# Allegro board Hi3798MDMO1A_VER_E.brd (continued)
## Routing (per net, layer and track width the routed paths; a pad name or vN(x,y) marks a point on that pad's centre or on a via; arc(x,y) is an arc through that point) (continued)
DDR_DQ9: length 9.5
  TOP w0.127: U3.C3 42.75,43.45 43.15,43.05 45.28,43.05 48.54,39.8 49.61,39.8 50.01,39.4 U1.K2
DDR_DQ10: length 12.4
  TOP w0.127: U1.M5 52.72,37.8 v2(52.32,37.4) ; v2(42.92,39.85) U3.C8
  BOTTOM w0.127: v2(52.32,37.4) 51.92,37.8 48.4,37.8 45.31,40.89 43.96,40.89 v2(42.92,39.85)
DDR_DQ11: length 14.7
  TOP w0.127: U1.J3 50.72,39.8 50.12,39.8 49.51,40.41 48.49,40.41 44.93,43.97 44.93,45.72 44.54,46.1 42.39,46.1 42.12,45.84 42.12,44.65 U3.C2
DDR_DQ12: length 9.6
  TOP w0.127: v2(44.67,40.41) 44.51,40.25 U3.A7 ; U1.N4 v2(51.52,36.6)
  BOTTOM w0.127: v2(51.52,36.6) 50.99,37.13 48.44,37.13 45.15,40.41 v2(44.67,40.41)
DDR_DQ13: length 9.8
  TOP w0.127: U3.A2 v2(44.52,44.65) ; U1.J4 v2(51.52,40.6)
  BOTTOM w0.127: v2(44.52,44.65) 45.99,44.65 49.65,40.99 50.88,40.99 51.13,40.99 v2(51.52,40.6)
DDR_DQ14: length 10.6
  TOP w0.127: U1.P4 v2(51.52,35.8) ; v2(43.72,39.85) U3.B8
  BOTTOM w0.127: v2(51.52,35.8) 51.35,35.8 50.53,36.62 48.31,36.62 45.08,39.85 v2(43.72,39.85)
DDR_DQ15: length 10.6
  TOP w0.127: U1.J5 v2(52.32,40.6) ; U3.A3 v2(44.52,43.85)
  BOTTOM w0.127: v2(52.32,40.6) 51.93,40.2 49.68,40.2 46.03,43.85 v2(44.52,43.85)
DDR_DQ16: length 17.1
  TOP w0.127: U1.T5 v2(52.32,35) ; U6.E3 v2(40.52,27.44)
  BOTTOM w0.127: v2(40.52,27.44) 40.52,28.1 41.24,28.83 41.24,29.34 46.93,35.02 50.26,35.02 50.68,34.6 51.93,34.6 v2(52.32,35)
DDR_DQ17: length 20.1
  TOP w0.127: U6.F7 40.51,23.45 40.51,22.83 40.68,22.66 41.16,22.66 41.31,22.52 41.31,21.27 41.75,20.83 44.92,20.83 52.03,27.93 52.03,29.26 52.28,29.51 52.28,29.89 52.72,30.33 U1.AA5
DDR_DQ18: length 13.7
  TOP w0.127: U6.F2 40.52,28.25 40.52,28.87 46.32,34.67 48.47,34.67 48.8,35 49.67,35 50.06,34.6 U1.T2
DDR_DQ19: length 19.4
  TOP w0.127: U1.AB5 52.72,29.52 52.31,29.1 52.31,27.67 45.08,20.45 41.35,20.45 40.51,21.28 40.51,22.4 40.12,22.79 U6.F8
DDR_DQ20: length 18.8
  TOP w0.127: U1.R5 v2(52.32,35.8) ; U6.H3 v2(38.92,27.44)
  BOTTOM w0.127: v2(52.32,35.8) 51.93,35.4 50.86,35.4 50.58,35.68 46.95,35.68 40.86,29.59 40.86,28.96 40.1,28.19 40.1,27.81 39.73,27.44 v2(38.92,27.44)
DDR_DQ21: length 21.7
  TOP w0.127: U1.AC6 53.52,27.67 45.54,19.68 40.71,19.68 38.89,21.51 38.89,22.4 38.52,22.77 U6.H8
DDR_DQ22: length 15.9
  TOP w0.127: U1.T3 50.83,34.6 50.46,34.97 50.2,34.97 49.92,35.25 48.6,35.25 48.4,35.05 46.06,35.05 40.86,29.84 40.1,29.84 39.72,29.46 39.72,28.24 U6.G2
DDR_DQ23: length 23.3
  TOP w0.127: U6.H7 38.92,23.44 38.92,22.85 39.11,22.66 39.51,22.66 39.69,22.49 39.69,21.34 40.97,20.07 45.34,20.07 53.15,27.88 53.15,30.22 U1.AA6
DDR_DQ24: length 17.6
  TOP w0.127: U6.D7 42.12,23.44 42.12,22.8 42.28,22.64 42.79,22.64 42.94,22.49 42.94,21.6 43.33,21.21 44.75,21.21 51.72,28.18 51.72,29.36 51.49,29.59 51.49,30.17 U1.AA4
DDR_DQ25: length 11.3
  TOP w0.127: U6.C3 42.92,27.45 42.92,30 46.72,33.8 U1.U1
DDR_DQ26: length 13
  TOP w0.127: U6.C8 42.83,23.04 43.23,22.65 45.63,22.65 51.47,28.49 51.47,29.18 51.12,29.53 U1.AB3
DDR_DQ27: length 13.2
  TOP w0.127: U6.C2 42.11,28.25 42.11,29.82 46.5,34.21 48.58,34.21 48.68,34.11 49.17,34.11 49.26,34.21 50.71,34.21 U1.U3
DDR_DQ28: length 8.3
  TOP w0.127: U1.AC2 45.32,23.99 44.27,23.99 U6.A7
DDR_DQ29: length 11.4
  TOP w0.127: U1.T4 v2(51.52,34.2) ; U6.A2 44.63,27.84 v2(45.03,28.24)
  BOTTOM w0.127: v2(45.03,28.24) 45.03,29.69 49.53,34.2 v2(51.52,34.2)
DDR_DQ30: length 10.9
  TOP w0.127: U1.AB2 50.73,29.39 50.73,28.88 45.31,23.45 43.72,23.45 U6.B8
DDR_DQ31: length 12.6
  TOP w0.127: U1.U4 v2(52.32,34.2) ; U6.A3 v2(44.52,27.44)
  BOTTOM w0.127: v2(44.52,27.44) 45.06,27.44 45.69,28.07 45.69,29.46 50.03,33.8 51.93,33.8 v2(52.32,34.2)
DDR_DQS0N: length 13
  TOP w0.114: U1.L1 49.43,38.69 49.27,38.69 49.16,38.58 49.16,38.47 49.05,38.35 48.82,38.35 48.7,38.47 48.7,38.58 48.59,38.69 48.4,38.69 45.05,42.04 40.1,42.04 39.58,42.55 39.58,43.19 U3.G3
DDR_DQS0P: length 13.1
  TOP w0.114: U1.L2 49.96,38.96 48.51,38.96 45.16,42.3 40.21,42.3 39.85,42.66 39.85,43.19 U3.F3
DDR_DQS1N: length 10.3
  TOP w0.114: U3.B7 43.05,40.52 43.05,40.71 43.24,40.89 44.93,40.89 48.37,37.45 50.77,37.45 U1.M3
DDR_DQS1P: length 10.3
  TOP w0.114: U1.M2 50.24,37.71 49.93,37.71 49.81,37.83 49.81,37.99 49.7,38.1 49.47,38.1 49.35,37.99 49.35,37.83 49.24,37.71 48.48,37.71 45.04,41.16 43.13,41.16 42.78,40.82 42.78,40.52 U3.C7
DDR_DQS2N: length 17.5
  TOP w0.114: U1.V2 50.24,33.08 50.08,33.08 49.94,32.94 49.7,32.94 49.57,33.08 49.32,33.08 49.19,32.94 48.95,32.94 48.81,33.08 48.57,33.08 48.44,32.94 48.2,32.94 48.06,33.08 47.86,33.08 45.69,30.91 45.69,27.14 44.29,25.74 40.02,25.74 39.71,26.05 39.71,26.65 U6.G3
DDR_DQS2P: length 17.5
  TOP w0.114: U1.V3 50.9,33 50.55,33.35 47.75,33.35 45.42,31.02 45.42,27.25 44.18,26 40.13,26 39.97,26.16 39.97,26.9 U6.F3
DDR_DQS3N: length 13
  TOP w0.114: U1.W2 50.02,32.2 49.61,31.8 48.78,31.8 48.61,31.62 48.61,28.45 44.8,24.64 43.28,24.64 43.05,24.41 43.05,24.11 U6.B7
DDR_DQS3P: length 12.9
  TOP w0.114: U1.W1 49.39,32.06 48.67,32.06 48.34,31.73 48.34,31.45 48.23,31.33 48.23,31.09 48.34,30.98 48.34,30.74 48.23,30.62 48.23,30.38 48.34,30.27 48.34,30.03 48.23,29.91 48.23,29.67 48.34,29.56 48.34,29.31 48.23,29.2 48.23,28.96 48.34,28.84 48.34,28.56 44.68,24.9 43.17,24.9 42.78,24.52 42.78,24.11 U6.C7
DDR_ODT: length 85.5
  TOP w0.127: U3.K1 v2(37.32,44.65) ; U6.K1 37.23,28.95 37.23,29.8 v2(36.89,30.13) 36.61,30.41 36.61,30.41 33.08,33.94 v2(29.81,33.94) ; U1.AB15 v2(61.12,29.4)
  BOTTOM w0.127: v2(36.89,30.13) 36.61,30.41 36.61,37.71 36.97,38.07 36.97,40.85 36.57,41.26 36.57,43.9 v2(37.32,44.65) ; v2(29.81,33.94) 28.03,32.17 28.03,27.43 29.43,26.04 29.43,25.65 28.81,25.04 28.81,21.19 32.52,17.48 32.52,16.43 36,12.95 46.69,12.95 60.73,26.99 60.73,29 v2(61.12,29.4)
DDR_PLL: length 9.7
  TOP w0.254: v2(57.92,35) 57.91,35 56.59,35 55.55,35 55.01,35.55 v2(55.01,36.47)
  TOP w0.305: U1.N8 55.12,36.58 v2(55.01,36.47) ; U1.T12 v2(57.92,35)
  BOTTOM w0.381: v2(57.92,35) 57.92,35 C270.1 ; LB7.1 54.53,38.61 54.53,38.07 54.86,37.74 C11.1 54.86,36.62 v2(55.01,36.47) 55.01,36.15 C264.1
DDR_RASN: length 90
  TOP w0.127: U1.AB16 v2(61.12,30.2) ; U6.J3 38.06,27.39 38.06,28.96 37.81,29.21 37.81,30.1 v2(37.05,30.86) 33.31,34.6 v2(29.81,34.6) ; U3.J3 v2(37.32,43.85)
  BOTTOM w0.127: v2(61.12,30.2) 61.55,29.77 61.55,26.74 47,12.19 35.68,12.19 31.46,16.41 31.46,17.91 27.65,21.72 27.65,32.45 v2(29.81,34.6) ; v2(37.32,43.85) 36.79,43.33 36.79,41.41 37.28,40.93 37.28,37.9 37,37.62 37,30.92 v2(37.05,30.86)
DDR_RESETN: length 76.5
  TOP w0.127: v1(36.92,14.22) 32.46,14.22 28.49,18.19 28.49,25.35 29.91,26.76 C314.1 30.34,26.78 30.45,26.67 32.23,26.67 32.46,26.9 32.46,27.33 32.12,27.67 U6.T2 31.56,27.84 27.48,31.93 27.48,36.27 28.42,37.21 28.42,41.8 29.71,43.09 32.32,43.09 32.52,43.29 v2(32.52,43.85) U3.T2 ; U1.AB13 v2(59.52,29.4)
  BOTTOM w0.127: v2(32.52,43.85) 32.51,43.85 C313.1 ; v2(59.52,29.4) 59.4,29.28 R24.1 58.92,28.6 58.26,27.94 58.26,27.05 45.43,14.22 v1(36.92,14.22)
DDR_VREF_A_CA: length 6.8
  TOP w0.203: 35.93,38.19 35.72,38.39 35.72,39.05 U3.M8
  TOP w0.381: R55.1 C86.1 R33.2 C49.2 35.75,36.44 35.93,36.61 35.93,38.19
DDR_VREF_A_DQ: length 3.9
  TOP w0.254: U3.H1 v2(38.12,45.45)
  BOTTOM w0.381: v2(38.12,45.45) 37.91,45.66 C208.2 R54.2 C271.1 R75.1
DDR_VREF_B_CA: length 6.6
  TOP w0.203: 35.97,21.65 35.7,21.92 35.7,22.66 U6.M8
  TOP w0.381: R93.1 C87.1 R92.2 C66.2 36.08,21.54 35.97,21.65
DDR_VREF_B_DQ: length 4.5
  TOP w0.305: v2(38.59,29.7) 38.59,28.72 U6.H1
  BOTTOM w0.381: v2(38.59,29.7) 38.7,29.81 C308.1 R84.1 C223.2 R78.2
DDR_WEN: length 75.3
  TOP w0.127: U1.Y13 59.12,31.4 v2(58.72,31) ; v1(33.9,16.76) 33.58,17.08 30.83,19.83 30.83,23.71 31.76,24.64 34.52,24.64 36.12,26.24 U6.L3 36.12,27.28 35.66,27.73 35.66,27.99 35.37,28.28 35.12,28.28 34.91,28.48 34.91,29.45 34.26,30.1 32.61,30.1 31.97,30.73 31.34,30.73 29,33.07 29,35.26 29.94,36.2 29.94,39.24 31.63,40.93 34.18,40.93 36.12,42.87 U3.L3
  BOTTOM w0.127: v2(58.72,31) 58.72,28.91 57.88,28.07 57.88,27.3 45.31,14.73 35.93,14.73 v1(33.9,16.76)
FE_1V1: length 1.3
  TOP w0.305: U1.G10 v2(56.32,41.4)
  BOTTOM w0.381: C248.1 56.17,41.25 v2(56.32,41.4)
FE_3V3: length 0.6
  TOP w0.305: U1.E5 52.72,43.4 v2(52.32,43.8)
HDMI_TX0N: length 42.9
  TOP w0.114: J26.9 47.72,78.17 47.29,77.74 47.29,76.95 46.54,76.2 46.54,75.76 46.65,75.64 U24.9 U24.2 46.65,73.64 46.54,73.52 46.54,67.6 50.4,63.74 50.4,59.96 59.36,51 59.36,50.19 61.86,47.69 61.86,44.54 U1.D16
HDMI_TX0P: length 42.9
  TOP w0.114: U1.C16 61.6,45.07 61.6,46.4 61.44,46.56 61.44,46.86 61.6,47.02 61.6,47.58 61.49,47.69 61.33,47.69 61.25,47.61 61.09,47.61 60.93,47.78 60.93,47.94 61,48.01 61,48.17 60.84,48.33 60.68,48.33 60.61,48.26 60.44,48.26 60.28,48.42 60.28,48.58 60.36,48.66 60.36,48.82 59.09,50.08 59.09,50.89 50.13,59.85 50.13,63.63 46.27,67.49 46.27,73.51 46.15,73.63 U24.1 U24.10 46.15,75.62 46.27,75.74 46.27,76.31 47.02,77.06 47.02,77.8 46.72,78.11 J26.7
HDMI_TX1N: length 42
  TOP w0.114: J26.6 46.22,78.23 45.75,77.76 45.75,76.98 44.86,76.09 44.86,75.81 44.98,75.69 U23.6 U23.5 44.98,73.7 44.87,73.58 44.87,67.85 49.38,63.33 49.38,58.77 57.41,50.75 57.75,50.75 58.35,50.15 58.35,49.97 58.35,49.8 61.07,47.08 61.07,46.57 61.07,46.15 U1.B15
HDMI_TX1P: length 42
  TOP w0.114: J26.4 45.22,78.08 45.49,77.82 45.49,77.09 44.6,76.2 44.6,75.81 44.48,75.7 U23.7 U23.4 44.48,73.69 44.6,73.57 44.6,67.74 49.12,63.22 49.12,58.66 57.3,50.48 57.64,50.48 58.08,50.04 58.08,49.69 58.79,48.99 58.79,48.83 58.71,48.76 58.71,48.6 58.87,48.43 59.04,48.43 59.11,48.51 59.27,48.51 59.43,48.34 59.43,48.18 59.36,48.11 59.36,47.95 59.52,47.79 59.68,47.79 59.76,47.86 59.92,47.86 60.08,47.7 60.08,47.54 60.08,47.36 60.22,47.21 60.4,47.21 60.56,47.21 60.8,46.97 60.8,46.68 U1.A15
HDMI_TX2N: length 42.9
  TOP w0.114: J26.3 44.72,78.12 44.38,77.79 44.38,77.3 43.36,76.28 43.36,75.73 43.48,75.61 U23.9 U23.2 43.48,73.57 43.35,73.44 43.35,67.76 48.37,62.75 48.37,58.39 60.28,46.47 60.28,45.36 U1.C14
HDMI_TX2P: length 42.8
  TOP w0.114: U1.B14 60.02,45.89 60.02,46.36 59.8,46.58 59.64,46.58 59.56,46.5 59.4,46.5 59.24,46.66 59.24,46.82 59.32,46.9 59.32,47.06 59.16,47.22 59,47.22 58.92,47.14 58.75,47.14 58.59,47.3 58.59,47.47 58.67,47.55 58.67,47.71 48.1,58.28 48.1,62.64 43.08,67.65 43.08,73.53 42.98,73.64 U23.1 U23.10 42.98,75.62 43.1,75.74 43.1,76.39 44.12,77.41 44.12,77.75 43.72,78.14 J26.1
HDMI_TX_1V1: length 1.1
  TOP w0.305: U1.G14 59.92,41.8 v2(60.32,41.4) U1.G15
HDMI_TX_3V3: length 0.6
  TOP w0.381: U1.E15 v2(60.32,43.8)
HDMI_TX_CEC: length 42.3
  TOP w0.127: J26.13 49.72,75.89 48.8,74.98 48.8,72.94 49.28,72.47 50.31,72.47 U4.3 50.31,71.89 49.92,71.5 R268.2 49.92,66.63 52.36,64.2 52.36,61.43 61.18,52.6 61.18,51.69 61.59,51.28 61.59,50.2 63.03,48.76 63.03,45.64 63.12,45.54 U1.C18
HDMI_TX_HOTPLUG: length 42.5
  TOP w0.127: U1.B19 63.92,45.8 63.92,46.08 64.32,46.48 64.32,46.88 63.79,47.42 63.79,49.14 62.58,50.35 62.58,51.82 61.94,52.45 61.94,53.06 53.76,61.25 53.76,68.5 52.84,69.41 C149.1 R8.2 52.84,71.89 52.81,71.91 U4.4 54.43,72.47 55.66,73.71 55.66,75.22 54.42,76.46 54.42,76.77 52.72,78.47 J26.19
HDMI_TX_SCL: length 42.7
  TOP w0.127: U1.D18 63.51,44.59 63.51,45.69 63.28,45.92 63.28,48.89 61.92,50.25 61.92,51.46 61.44,51.94 61.44,52.76 52.74,61.45 52.74,67.12 51.39,68.46 51.39,74.03 51.05,74.37 U4.1 50.31,75.35 50.69,75.73 R186.1 51.19,76.4 50.72,76.87 J26.15
HDMI_TX_SDA: length 40.1
  TOP w0.127: J26.16 51.22,78.09 52.97,76.34 R187.1 52.97,75.23 52.81,75.08 U4.6 52.07,74.37 51.75,74.05 51.75,68.62 53.12,67.25 53.12,61.48 61.69,52.91 61.69,52.2 62.25,51.64 62.25,50.3 63.53,49.02 63.53,46.98 U1.A19
HDMI_TXCN: length 42.4
  TOP w0.114: J26.12 49.22,78.23 48.84,77.85 48.84,77.04 48.04,76.23 48.04,75.75 48.15,75.64 U24.6 U24.5 48.15,73.62 48.05,73.52 48.05,67.61 51.42,64.25 51.42,60.46 55.86,56.02 57.73,54.15 57.9,54.15 58.03,54.28 58.41,54.28 58.89,53.8 58.89,53.42 58.76,53.28 58.76,53.12 59.08,52.8 59.24,52.8 59.38,52.93 59.76,52.93 60.24,52.45 60.24,52.07 60.11,51.94 60.11,51.77 60.47,51.41 60.47,50.48 62.67,48.28 62.67,46.15 U1.B17
HDMI_TXCP: length 42.4
  TOP w0.114: J26.10 48.22,78.21 48.58,77.85 48.58,77.15 47.77,76.34 47.77,75.79 47.65,75.67 U24.7 U24.4 47.65,73.65 47.79,73.52 47.79,67.5 51.15,64.14 51.15,60.35 57.62,53.88 58.01,53.88 58.14,54.01 58.3,54.01 58.63,53.69 58.63,53.53 58.49,53.39 58.49,53.01 58.97,52.53 59.35,52.53 59.49,52.67 59.65,52.67 59.97,52.34 59.97,52.18 59.84,52.05 59.84,51.66 60.2,51.3 60.2,50.37 60.4,50.17 60.4,50.01 60.36,49.97 60.36,49.81 60.52,49.65 60.68,49.65 60.72,49.69 60.88,49.69 61.04,49.53 61.04,49.36 61,49.32 61,49.16 61.16,49 61.33,49 61.37,49.04 61.53,49.04 61.69,48.88 61.69,48.72 61.65,48.68 61.65,48.51 61.81,48.35 61.97,48.35 62.01,48.39 62.18,48.39 62.4,48.17 62.4,46.68 U1.A17
IR_IN: length 33.6
  TOP w0.127: v1(70.4,11.05) 70.07,11.05 69.74,10.72 69.74,9.45 69.35,9.06 69.35,6.29 69.66,5.99 R140.1 70.14,4.87 70.09,4.82 D3.1 ; v1(65.87,25.62) 65.69,25.8 65.69,29.84 65.18,30.36 65.18,31.05 U1.Y21
  BOTTOM w0.127: v1(65.87,25.62) 65.87,25.03 69.06,21.84 69.06,15.88 71.34,13.59 71.34,12.95 70.4,12.01 v1(70.4,11.05)
LED0_BASE: length 44.8
  TOP w0.127: U1.B2 49.93,45.41 49.3,45.41 48.86,45.85 48.86,47.35 49.24,47.73 49.24,49.66 41.32,57.58 28.24,57.58 26,59.82 26,61.2 24.21,62.99 20.8,62.99 20.1,63.69 20.1,64.76 R26.2 R67.2
LED0_LINK_ACT: length 30.4
  TOP w0.127: v1(37.75,58.09) 41.45,58.09 49.62,49.91 49.62,47.66 49.12,47.15 49.12,46.2 U1.B1 ; R30.2 R79.2 v2(37.75,66.18)
  BOTTOM w0.127: v1(37.75,58.09) 38.7,59.04 38.7,65.23 v2(37.75,66.18)
LED_GREEN: length 29.3
  TOP w0.127: U1.AB22 65.95,29.42 65.95,26.31 v1(66.73,25.52)
  BOTTOM w0.127: R48.1 67.28,9.72 66.95,9.4 66.58,9.4 R3.2 ; R48.1 67.65,9.27 67.78,9.14 69.69,9.14 70.87,10.33 70.87,11.98 71.72,12.83 71.72,13.72 69.44,16 69.44,22.23 66.73,24.93 v1(66.73,25.52) ; R48.1 R22.1
LED_RED: length 27.3
  TOP w0.127: v1(67.47,25.07) 67.47,25.51 66.28,26.7 66.28,28.59 66.32,28.63 U1.AC22
  BOTTOM w0.127: v1(67.47,25.07) 69.82,22.72 69.82,16.13 72.1,13.84 72.1,12.7 71.18,11.78 71.18,10.12 69.51,8.45 R60.2 R39.1 R31.1
MUTE_CTRL: length 31.6
  TOP w0.127: R90.1 55.66,70.17 54.14,68.65 54.14,61.27 62.2,53.21 62.2,52.67 64.8,50.06 64.8,47.42 65.08,47.14 65.08,46.43 64.86,46.2 64.59,46.2 64.31,45.93 64.31,45.39 U1.C19
NF_ALE_EMMC_PWREN: length 33.3
  TOP w0.127: U19.17 84.01,47.27 83.25,48.03 80.26,48.03 79.98,47.75 79.98,45.59 81.25,44.32 81.25,37.97 79.48,36.2 68.25,36.2 68.13,36.09 66.23,36.09 65.72,36.6 65.12,36.6 U1.N20
NF_CLE: length 33
  TOP w0.127: U1.N21 65.75,37 66.4,36.34 67.98,36.34 68.09,36.46 79.22,36.46 80.87,38.1 80.87,44.2 79.65,45.42 79.65,47.83 80.13,48.31 83.61,48.31 84.51,47.41 U19.16
NF_CSN0_EMMC_CMD: length 47.7
  TOP w0.127: v2(85.35,40.89) 85.35,41.06 87.54,43.25 87.54,44.32 88.01,44.8 U19.9 88.01,47.34 86.76,48.59 80,48.59 79.32,47.9 79.32,45.24 80.49,44.07 80.49,38.23 78.97,36.71 67.89,36.71 67.78,36.6 66.72,36.6 U1.N22
  TOP w0.254: v2(87.22,38.36) 87.51,38.66 U22.W5
  BOTTOM w0.127: v2(87.22,38.36) 86.7,37.85 86.33,37.85 85.86,38.32 85.86,39.84 85.57,40.12 R212.2 85.22,40.76 85.35,40.89 v2(85.35,40.89)
NF_DQ0_EMMC_D0: length 36.4
  TOP w0.127: v2(88.74,32.26) 88.51,32.48 U22.H3 ; v2(84.93,30.61) 84.55,30.61 82.51,28.57 U19.29 82.51,26.04 82.31,25.83 80.29,25.83 79.62,26.49 79.62,33.21 77.81,35.02 68.28,35.02 67.91,35.4 U1.R23
  BOTTOM w0.127: v2(88.74,32.26) 88.61,32.38 86.2,32.38 84.97,31.15 84.97,30.64 v2(84.93,30.61) 84.57,30.25 R189.2
NF_DQ1_EMMC_D1: length 36.3
  TOP w0.102: U1.R22 66.66,35.06 67.87,35.06 68.16,34.77
  TOP w0.127: 68.16,34.77 77.63,34.77 79.29,33.11 79.29,26.44 80.16,25.57 82.58,25.57 83.01,26 U19.30 v1(83.01,28.07) ; v2(87.6,31.5) 88.01,31.91 U22.H4
  BOTTOM w0.127: v2(87.6,31.5) 87.09,32 86.43,32 85.57,31.14 85.57,30.48 83.91,28.83 R12.2 82.92,28.16 v1(83.01,28.07)
NF_DQ2_EMMC_D2: length 37
  TOP w0.102: U1.R21 66.09,34.83 67.72,34.83 68.06,34.49
  TOP w0.127: v2(86.58,31.5) 86.58,31.75 87.51,32.68 U22.H5 ; 68.06,34.49 77.43,34.49 78.96,32.95 78.96,26.4 80.81,24.56 82.95,24.56 83.12,24.73 R29.2 83.51,25.46 U19.31 83.51,28.05 84.68,29.21 v2(85.57,29.21)
  BOTTOM w0.127: v2(86.58,31.5) 86.07,30.99 86.07,29.72 v2(85.57,29.21)
NF_DQ3_EMMC_D3: length 40.6
  TOP w0.089: U22.J2 88.76,33.62 88.76,33
  TOP w0.102: U1.T21 67.59,34.6 67.95,34.23
  TOP w0.127: 88.76,33 89.22,32.54 89.22,31.09 88.61,30.48 88.11,30.48 87.6,29.97 87.6,29.21 87.06,28.68 84.91,28.68 84.01,27.79 U19.32 84.01,24.95 R58.2 83.12,23.71 82.95,23.54 81.44,23.54 78.63,26.35 78.63,32.85 77.25,34.23 67.95,34.23
NF_DQ4_EMMC_D4: length 44.7
  TOP w0.089: U22.J3 88.26,33.62 88.26,33.01
  TOP w0.102: U1.T20 65.11,34.21 66.2,34.21 66.36,34.37 67.46,34.37 67.85,33.98
  TOP w0.127: v2(88.61,29.84) 88.11,29.34 88.11,28.6 88.51,28.19 U19.41 88.51,23.9 87.9,23.29 81.34,23.29 78.3,26.32 78.3,32.75 77.07,33.98 67.85,33.98 ; v2(88.74,31.24) 88.26,31.72 88.26,33.01
  BOTTOM w0.127: R176.2 89.84,31.24 v2(88.74,31.24) 88.61,31.11 v2(88.61,29.84)
NF_DQ5_EMMC_D5: length 45.8
  TOP w0.089: 87.76,33.06 87.76,33.62 U22.J4
  TOP w0.102: 67.75,33.73 67.34,34.14 66.66,34.14 U1.U22
  TOP w0.127: v2(87.6,30.61) 87.09,31.11 87.09,31.75 87.76,32.42 87.76,33.06 ; 67.75,33.73 76.84,33.73 77.97,32.6 77.97,26.29 81.23,23.03 88.15,23.03 89.01,23.9 U19.42 89.01,28.56 v2(88.61,28.96)
  BOTTOM w0.127: R177.2 89.75,31.75 88.61,31.75 87.6,30.73 v2(87.6,30.61) 87.6,29.97 v2(88.61,28.96)
NF_DQ6_EMMC_D6: length 46.6
  TOP w0.089: 87.26,33.22 87.26,33.52 87.51,33.77 U22.J5
  TOP w0.127: 87.26,33.22 87.26,32.94 86.07,31.75 86.07,31.11 v2(86.58,30.61) ; U1.U23 67.45,33.47 76.64,33.47 77.64,32.47 77.64,26.2 81.06,22.78 88.41,22.78 89.51,23.89 U19.43 89.51,29.33 v2(89.38,29.46)
  BOTTOM w0.127: v2(86.58,30.61) 86.58,30.23 88.36,28.45 89.12,28.45 89.38,28.7 v2(89.38,29.46) 89.38,29.72 89.67,30.02 90.05,30.02 R188.2
NF_DQ7_EMMC_D7_BOOT_SEL0: length 48.3
  TOP w0.089: U22.J6 86.76,33.62 86.76,32.99 86.52,32.74
  TOP w0.127: 86.52,32.74 85.69,31.92 85.69,30.48 86.58,29.59 v2(86.58,29.21) ; U1.U21 66.1,33.22 69.63,33.22 R82.1 70.39,33.22 76.46,33.22 77.31,32.37 77.31,26.15 80.93,22.53 88.66,22.53 90.01,23.88 U19.44 v1(90.01,28.07)
  BOTTOM w0.127: v2(86.58,29.21) 87.09,29.21 88.23,28.07 v1(90.01,28.07) 90.05,28.1 R202.2
NF_RDY0_EMMC_RST: length 53.5
  TOP w0.127: v2(90.62,37.33) 90.65,37.33 91.54,38.22 91.54,42.39 89.01,44.91 U19.7 89.01,47.35 87.22,49.15 79.75,49.15 78.66,48.06 78.66,44.88 79.72,43.81 79.72,38.48 79.09,37.85 68.8,37.85 68.23,37.27 67.65,37.27 67.53,37.38 65.93,37.38 U1.M21
  TOP w0.254: U22.U5 87.56,37.87 88,37.43 v2(88,35.99)
  BOTTOM w0.127: v2(88,35.99) 88,36.5 88.83,37.33 C115.1 R203.2 v2(90.62,37.33)
NF_REN_EMMC_CLK: length 42.3
  TOP w0.127: v2(86.16,40.89) 86.16,41.23 87.72,42.8 88.15,42.8 88.51,43.16 U19.8 88.51,47.34 86.99,48.87 79.88,48.87 78.99,47.98 78.99,45.06 80.1,43.94 80.1,38.35 79.09,37.34 R65.1
  TOP w0.254: U22.W6 87.01,38.84 86.54,38.37 v2(86.47,38.37)
  BOTTOM w0.127: v2(86.47,38.37) 86.16,38.68 v2(86.16,40.89)
NF_WEN_EMMC_DET: length 27.6
  TOP w0.127: U19.18 83.51,43.65 81.63,41.76 81.63,37.85 79.72,35.94 68.66,35.94 v2(68.33,35.61) 68.18,35.76 65.96,35.76 U1.P21
  BOTTOM w0.127: v2(68.33,35.61) 68.21,35.48 R56.2
NF_WP: length 5.2
  TOP w0.254: v2(82.66,43.58) 83.01,43.94 U19.19
  BOTTOM w0.381: v2(82.66,43.58) 82.08,43 R89.1 R215.2
PWR_OFF/ON: length 2.9
  TOP w0.127: R44.1 R51.1 68.32,40.67 67.85,40.2 U1.J23
RECOVERY: length 51.9
  TOP w0.127: U1.J22 66.32,40.41 65.95,40.79 65.95,41.55 67.62,43.23 67.62,45.03 67.9,45.31 67.9,47.47 66.25,49.12 66.25,50.95 63.98,53.22 63.98,61.19 66.54,63.75 69.18,63.75 71.28,65.85 71.28,75.14 R47.2 C42.2 70.61,83.85 S1.2
RF0: length 8.6
  TOP w0.127: L1.2 C64.1 17.48,11.83 arc(17.77,11.89) 18,12.05 20.17,14.22 arc(20.83,15.2) 21.07,16.37 U7.3
RF1: length 4
  TOP w0.127: L7.2 C50.1 17.64,15.13 arc(17.97,15.64) 18.09,16.24 U2.7
RFF0: length 3
  TOP w0.127: J5.1 13.73,10.84 arc(13.98,10.89) 14.19,11.03 arc(14.34,11.24) 14.39,11.49 C61.1 L1.1
RFF1: length 3
  TOP w0.127: J4.1 13.72,15.68 arc(13.97,15.63) 14.19,15.48 arc(14.33,15.27) 14.39,15.01 C60.1 L7.1
RX+_PHY0: length 35.1
  TOP w0.114: R63.1 29.81,60.81 29.81,60.45 30.45,59.81 31.5,59.81 31.62,59.69 U8.6 U8.3 33.6,59.69 33.72,59.81 43.41,59.81 52.35,50.87 52.35,49.07 52.62,48.8 52.93,48.8 53.04,48.69 53.04,48.23 52.93,48.12 52.62,48.12 52.35,47.85 52.35,44.57 U1.D5
RX-_PHY0: length 35.1
  TOP w0.114: U1.C5 52.61,45.11 52.61,45.47 52.73,45.59 52.94,45.59 53.05,45.7 53.05,45.93 52.94,46.04 52.73,46.04 52.61,46.16 52.61,47.73 52.73,47.85 53.04,47.85 53.31,48.12 53.31,48.8 53.04,49.07 52.73,49.07 52.61,49.18 52.61,50.98 43.52,60.08 33.72,60.08 33.6,60.2 U8.4 U8.5 31.62,60.2 31.5,60.08 30.56,60.08 30.08,60.56 30.08,60.95 30.19,61.06 R64.1
SDIO0_CARD_DETECT: length 46.5
  TOP w0.127: J21.9 v1(15.82,61.78) ; v1(21.83,55.52) 24.71,55.52 26.64,53.59 39.97,53.59 45.05,48.51 45.05,48.26 46.7,46.61 46.7,44.7 48.81,42.6 U1.F1
  BOTTOM w0.127: v1(15.82,61.78) 17.74,59.86 17.74,56.64 17.94,56.43 20.94,56.43 21.14,56.23 R155.2 21.91,55.6 v1(21.83,55.52)
SDIO0_CCLK_OUT: length 39.6
  TOP w0.127: J21.5 12.77,56.54 12.94,56.71 16.67,56.71 17.92,57.96 25.83,57.96 27.35,56.43 40.32,56.43 R5.1
SDIO0_CCMD: length 48.8
  TOP w0.127: U1.E2 49.91,43.81 48.74,43.81 47.47,45.09 47.47,47.44 46.77,48.13 46.77,49.34 40.05,56.05 27.1,56.05 25.58,57.58 18.38,57.58 14.78,53.98 v1(13.12,53.98) 12.76,54.34 J21.3
  BOTTOM w0.127: R153.2 13.13,53.97 v1(13.12,53.98)
SDIO0_CDATA0: length 48.7
  TOP w0.127: J21.7 v1(13.14,58.74) 13.5,59.1 17.18,59.1 17.94,58.34 26.08,58.34 27.61,56.82 40.82,56.82 47.97,49.66 47.97,45.34 48.97,44.34 50.73,44.34 50.88,44.2 U1.D3
  BOTTOM w0.127: R152.2 13.22,58.82 v1(13.14,58.74)
SDIO0_CDATA1: length 48.3
  TOP w0.127: J21.8 v1(13.14,59.84) 13.5,59.48 17.43,59.48 18.2,58.72 26.34,58.72 27.86,57.2 41.07,57.2 48.35,49.91 48.35,48.64 48.23,48.51 48.23,45.47 49.1,44.6 49.92,44.6 U1.C2
  BOTTOM w0.127: v1(13.14,59.84) 13.85,59.84 R151.2
SDIO0_CDATA2: length 50
  TOP w0.127: U1.F2 49.9,43.02 48.77,43.02 46.96,44.83 46.96,46.86 45.43,48.39 45.43,48.64 40.1,53.98 26.88,53.98 24.67,56.18 19.67,56.18 17.81,54.32 17.81,52.75 15.93,50.87 14.31,50.87 v1(13.04,52.14) J21.1
  BOTTOM w0.127: R156.2 13.5,51.68 v1(13.04,52.14)
SDIO0_CDATA3: length 47.9
  TOP w0.127: U1.E1 48.77,43.4 47.21,44.96 47.21,47.18 46.39,48.01 46.39,49.08 39.8,55.67 26.85,55.67 25.32,57.2 18.68,57.2 14.49,53.01 v1(13.11,53.01) 12.87,53.24 J21.2
  BOTTOM w0.127: R154.2 13.29,52.83 v1(13.11,53.01)
SDIO0_CWPR: length 4.1
  TOP w0.127: U1.C1 49.2,45 48.61,45.59 48.61,47.68 v2(48.75,47.82)
  BOTTOM w0.127: R25.2 48.68,47.75 v2(48.75,47.82)
SDIO0_PWREN: length 27.2
  TOP w0.127: R76.1 29.53,52.78 R149.1 40.03,52.78 46.45,46.35 46.45,44.58 48.79,42.24 50.76,42.24 U1.F3
SDIO_3318: length 61.9
  TOP w0.254: v2(45.93,48.77) 40.22,54.48 27.27,54.48 25.07,56.69 19.14,56.69 15.58,53.13 v1(15.58,51.35)
  TOP w0.305: U1.G5 v2(53.12,41.4)
  BOTTOM w0.254: C22.2 53.04,42.13 52.51,42.67 50.13,42.67 45.93,46.87 v2(45.93,48.77)
  BOTTOM w0.305: C22.2 53.04,41.48 v2(53.12,41.4) ; R151.1 R152.1 14.67,58.44 14.36,58.14 12.97,58.14 12.48,57.65 12.48,55.06 12.89,54.66 14.57,54.66 14.77,54.45 R153.1 R154.1 R156.1 15.1,51.35 v1(15.58,51.35)
SPDIF_OUT_BOOT_SEL1: length 2.2
  TOP w0.127: U1.A20 64.72,47.12 64.3,47.54 R83.1
STANDBY_PWROFF: length 164.4
  TOP w0.127: v2(66.96,27.48) 66.61,27.83 66.61,28.55 66.73,28.67 66.73,29.41 U1.AB23 ; R35.1 v1(18.32,38.27) ; R98.1 73.82,17.56 73.85,17.58 v1(73.85,18.03)
  BOTTOM w0.127: R88.1 v2(66.96,27.48) 67.22,27.48 68.31,26.39 71.23,26.39 72.04,25.57 72.04,18.03 R81.1 73.06,17.72 73.37,18.03 v1(73.85,18.03) ; v1(73.85,18.03) 73.85,17.27 74.3,16.81 77.9,16.81 78.2,16.51 78.2,14.71 78.02,14.53 77.4,14.53 77.07,14.2 77.07,8.32 74.72,5.97 33.61,5.97 24.96,14.62 24.96,17.04 23.86,18.14 21.44,18.14 14,25.57 14,37.26 15.02,38.27 v1(18.32,38.27) ; v1(73.85,18.03) 73.95,18.13 73.95,20.36 78.33,24.74 78.33,35.94 75.28,38.99 75.28,47.75 73.53,49.5 R73.1
TX+_PHY0: length 33.9
  TOP w0.114: R59.1 27.4,60.81 27.4,59.69 28.3,58.79 31.5,58.79 31.62,58.67 U8.8 U8.1 33.6,58.67 33.72,58.79 42.5,58.79 43.2,58.09 50.95,50.35 50.95,47.69 51.57,47.07 51.57,46.15 U1.B4
TX-_PHY0: length 34
  TOP w0.114: R62.1 27.78,61.06 27.67,60.95 27.67,59.8 28.41,59.06 31.5,59.06 31.62,59.18 U8.7 U8.2 33.6,59.18 33.72,59.06 42.61,59.06 51.22,50.46 51.22,48.83 51.33,48.72 51.54,48.72 51.66,48.6 51.66,48.38 51.54,48.26 51.33,48.26 51.22,48.15 51.22,47.8 51.84,47.18 51.84,46.68 U1.A4
UART0_RXD: length 49.1
  TOP w0.127: J18.2 82.43,4.79 82.48,4.85 R136.2 87.52,5.25 89.27,7.01 89.27,9.95 87.77,11.45 87.77,16.96 83.01,21.72 80.73,21.72 76.23,26.21 69.88,26.21 68.42,27.67 68.42,29.17 67.45,30.15 66.77,30.15 U1.AA22
UART0_TXD: length 51.4
  TOP w0.127: v1(83.12,4.54) 87.26,4.54 89.65,6.93 89.65,10.08 88.13,11.6 88.13,17.11 83.14,22.1 80.83,22.1 76.36,26.56 70.04,26.56 68.8,27.8 68.8,29.29 67.49,30.6 U1.AA23 ; R135.2 v1(80.7,4.49) 81.18,4.02 J18.3
  BOTTOM w0.127: v1(83.12,4.54) 83.07,4.49 v1(80.7,4.49)
USB0_DM: length 49
  TOP w0.127: U1.A6 v2(53.92,47)
  TOP w0.152: v1(81.67,61.35) 81.83,61.51 82.16,61.51 C95.1 D6.1 83.9,61.69 85.3,61.69 86.13,60.87 J12.2
  BOTTOM w0.152: v2(53.92,47) 53.73,46.81 53.53,46.81 53.37,46.96 53.37,47.68 53.53,47.83 53.53,48.11 53.37,48.26 53.37,48.54 53.53,48.69 53.53,48.97 53.37,49.12 53.37,49.4 53.53,49.55 53.53,49.83 53.37,49.99 53.37,50.27 53.53,50.42 53.53,50.7 53.37,50.85 53.37,51.13 53.53,51.28 53.53,51.56 53.37,51.71 53.37,51.99 53.53,52.15 53.53,52.43 53.37,52.58 53.37,52.86 53.53,53.01 53.53,53.29 53.37,53.44 53.37,53.72 53.53,53.87 53.53,54.15 53.37,54.3 53.37,55.55 57.31,59.48 62.52,59.48 67.22,64.18 78.52,64.18 81.07,61.64 81.39,61.64 v1(81.67,61.35)
USB0_DP: length 49.1
  TOP w0.127: U1.B6 v2(53.92,46.2)
  TOP w0.152: J12.3 86.11,62.85 85.27,62.02 83.79,62.02 D1.1 C92.1 82.22,62.15 81.77,62.15 v1(81.67,62.25)
  BOTTOM w0.152: v1(81.67,62.25) 81.39,61.97 81.21,61.97 78.66,64.51 67.08,64.51 62.38,59.81 57.17,59.81 53.04,55.68 53.04,46.76 53.37,46.43 53.69,46.43 v2(53.92,46.2)
USB01_1V1: length 0.6
  TOP w0.305: U1.G11 57.52,41.8 v2(57.92,41.4)
USB01_3V3: length 0.6
  TOP w0.305: U1.D7 v2(54.72,44.6)
USB1_DM: length 76.4
  TOP w0.152: U1.B7 54.39,45.87 54.39,46.94 54.87,47.43 54.87,47.68 54.72,47.83 54.54,47.83 54.39,47.98 54.39,48.28 54.54,48.44 54.72,48.44 54.87,48.59 54.87,49.73 43.85,60.75 37.63,60.75 37.3,61.08 37.3,61.58 37.11,61.77 v1(36.89,61.77) ; v1(21.24,32.18) 21.03,32.39 20.78,32.39 20.68,32.29 20.68,31.47 20.86,31.29 22.26,31.29 22.59,30.96 U7.7
  BOTTOM w0.152: v1(36.89,61.77) 37.17,61.48 37.17,60.51 34.95,58.29 30,58.29 25.05,53.35 25.05,40.26 23.52,38.73 20.34,38.73 19.91,38.3 19.91,37.64 19.08,36.81 J2.4 19.08,34.35 19.59,33.83 19.59,32.69 20.1,32.18 v1(21.24,32.18)
USB1_DP: length 76.4
  TOP w0.152: U1.C7 54.72,45.4 54.72,46.81 55.2,47.29 55.2,49.87 54.27,50.8 43.99,61.08 37.76,61.08 37.63,61.22 37.63,61.61 v1(37.78,61.77) ; U7.6 19.09,31.11 19.26,31.29 20.23,31.29 20.35,31.42 20.35,32.43 20.65,32.72 21.03,32.72 v1(21.24,32.94)
  BOTTOM w0.152: v1(21.24,32.94) 20.81,32.51 20.24,32.51 19.92,32.82 19.92,33.52 21.08,34.68 J2.3 21.08,36.81 20.24,37.64 20.24,38.16 20.48,38.4 23.66,38.4 25.38,40.13 25.38,53.21 30.13,57.96 35.09,57.96 37.5,60.37 37.5,61.48 v1(37.78,61.77)
USB3_DM: length 47.2
  TOP w0.152: U1.AC18 63.12,29.12 63.01,29.22 62.75,29.22 62.65,29.12 62.65,28.13 62.8,27.98 63.05,27.98 63.2,27.82 63.2,27.52 63.05,27.37 62.8,27.37 62.65,27.21 62.65,26.91 62.8,26.76 63.05,26.76 63.2,26.6 63.2,26.3 63.05,26.15 62.8,26.15 62.65,25.99 62.65,25.32 65.44,22.53 75.57,22.53 79.22,18.88 79.22,11.14 81.03,9.32 85.35,9.32 86.41,10.37 86.41,14.04 86.07,14.38 85.59,14.38 85.35,14.13 J13.2
USB3_DP: length 47.1
  TOP w0.152: J13.3 85.91,14.71 86.21,14.71 86.74,14.18 86.74,10.24 85.49,8.99 80.9,8.99 78.89,11 78.89,18.75 75.44,22.2 65.3,22.2 62.31,25.18 62.31,29.25 62.62,29.55 62.88,29.55 U1.AB18
USB3_RXN: length 28
  TOP w0.152: J13.5 83.85,17.65 83.61,17.42 82.84,17.42 82.21,18.04 82.21,19.41 77.04,24.58 66.15,24.58 65.31,25.42 65.31,29.21 U1.AB20
USB3_RXP: length 28
  TOP w0.152: J13.6 83.85,16.86 83.61,17.09 82.7,17.09 81.88,17.91 81.88,19.27 76.9,24.25 66.01,24.25 64.98,25.28 64.98,26.4 64.88,26.51 64.75,26.51 64.6,26.66 64.6,26.96 64.75,27.12 64.88,27.12 64.98,27.22 64.98,28.74 U1.AC20
USB3_TXN: length 31.2
  TOP w0.152: C77.2 80.59,13.89 80.59,19.13 76.12,23.59 65.77,23.59 64.17,25.19 64.17,27.53 64.32,27.68 64.4,27.68 64.55,27.83 64.55,28.14 64.4,28.29 64.32,28.29 64.17,28.44 64.17,28.76 63.84,29.09 63.84,29.38 63.97,29.51 64.19,29.51 64.32,29.64 64.32,29.92 64.19,30.04 63.94,30.04 63.84,30.15 63.84,30.52 63.9,30.58 U1.AA19
USB3_TXP: length 31.1
  TOP w0.152: U1.Y19 63.51,30.99 63.51,28.95 63.84,28.62 63.84,25.06 65.63,23.26 75.98,23.26 80.26,18.99 80.26,13.89 C81.2
USB_BOOT: length 9.8
  BOTTOM w0.127: 78.44,45.18 84.64,45.18 S2.2 ; 78.44,45.18 S2.1 ; 78.44,45.18 C89.1 R40.1
VDAC_3V3: length 2.6
  TOP w0.305: U1.G19 64,41.88 64,42.52 U1.F19 63.92,42.6 U1.E20 v2(65.12,43.8)
XIN: length 10.8
  TOP w0.203: U1.W23 68.01,32.2 70.04,30.17 70.37,30.17 R1.2 72.18,29.51 C364.1 72.36,29.41 73.14,30.2 75.14,30.2 75.61,29.73 X2.1
XOUT: length 7.4
  TOP w0.203: R14.1 71.71,30.3 R1.1 70.6,30.55 70.24,30.55 68.21,32.58 66.71,32.58 U1.W22
$4N774: length 3.4
  TOP w0.381: C43.1 R7.2 67.74,50.39 C71.1 67.43,49.44 R21.1
$4N775: length 7.1
  TOP w0.381: U11.6 73.35,52.24 R99.2 72.87,53.09 71.95,54 C76.1 R53.1 69.51,54 R70.1
$4N782: length 3.2
  TOP w0.127: v1(71.98,52.58) 71.62,52.58 71.37,52.32 U11.1
  BOTTOM w0.127: v1(71.98,52.58) 71.62,52.93 C8.1 R73.2
$4N811: length 5.3
  TOP w0.508: R13.2 71.88,11.98 71.41,11.98 71.21,12.18 U13.6 ; R13.2 72.27,11.98 72.27,11.42 71.69,10.84 R101.1 C82.1 ; R13.2 R110.1
$4N812: length 40.1
  TOP w0.127: v1(69.78,45.66) 69.52,45.4 C72.1 68.89,44.75 68.87,44.72 R23.1 ; R102.2 C45.1 72.27,15.36 73.25,16.33 73.25,20.4 v1(74.08,21.23)
  BOTTOM w0.127: v1(69.78,45.66) 70.76,45.66 74.9,41.53 74.9,38.86 77.95,35.81 77.95,25.1 v1(74.08,21.23)
$4N813: length 1
  TOP w0.381: R110.2 R102.1
$4N818: length 3.8
  TOP w0.381: v1(71.79,15.88) 71.47,15.88 70.83,15.24 U13.1
  BOTTOM w0.381: R81.2 C5.1 71.54,16.13 v1(71.79,15.88)
$4N881: length 5
  TOP w0.381: U15.5 15.11,40.52 14.77,40.18 R52.1 15.27,39.19 15.38,39.29 R10.1 C84.1
$4N883: length 3.3
  TOP w0.381: U15.1 18.94,39.97 19.11,39.8 R6.2 C30.1 20.07,38.35 R35.2
$4N953: length 3.3
  TOP w0.508: U14.5 v1(64.48,59.53)
  BOTTOM w0.381: v1(64.48,59.53) 64.77,59.82 R100.1 R105.1
$4N955: length 4.1
  TOP w0.508: U14.1 v1(72.36,55.72) 73.45,54.64 D4.1
  BOTTOM w0.381: v1(72.36,55.72) 72.24,55.6 R95.1
$4N956: length 1
  BOTTOM w0.381: C83.2 R104.1
$4N957: length 3.4
  TOP w0.508: U14.6 v1(64.48,58.26)
  BOTTOM w0.381: v1(64.48,58.26) 65.02,58.8 C24.1 C83.1
$4N958: length 2.8
  TOP w0.508: v1(64.48,56.61) 64.86,56.99 U14.7
  BOTTOM w0.381: R4.2 65.25,55.75 64.48,56.52 v1(64.48,56.61)
$4N975: length 2.6
  TOP w0.508: v1(64.48,55.34) 64.86,55.72 U14.8
  BOTTOM w0.381: C44.1 65.09,54.74 v1(64.48,55.34)
$4N980: length 1.1
  BOTTOM w0.381: R95.2 C65.1
$4N983: length 2.3
  TOP w0.508: U14.3 v1(72.36,58.26)
  BOTTOM w0.381: v1(72.36,58.26) 72.3,58.32 C65.2
$4N998: length 1
  TOP w0.381: R70.2 R7.1
$5N541: length 3.7
  TOP w0.381: R144.2 R118.2 75.32,19.63 75.62,19.32 75.62,18.44 Q4.3
$5N542: length 13.7
  TOP w0.127: v1(76.27,16.08) 76.22,16.13 76.22,16.27 75.93,16.56 75.35,16.56 74.96,16.94 R118.1
  BOTTOM w0.127: Q13.1 74.58,12.39 C6.2 76.11,13.91 76.11,15.92 v1(76.27,16.08) 76.93,15.42 Q14.1
$5N549: length 2.1
  TOP w0.381: R98.2 73.82,15.91 74.32,15.41 Q4.1
$6N188: length 2.8
  TOP w0.203: R14.2 C365.1 72.6,32 73.26,31.35 X2.3
$6N1407: length 1.6
  TOP w0.305: v2(53.12,43.8) 53.52,43.4 U1.E6
  BOTTOM w0.381: v2(53.12,43.8) 53.12,43.99 52.76,44.34 R173.1
$6N2001: length 2.5
  TOP w0.127: U1.Y17 v2(62.72,31.8)
  BOTTOM w0.127: v2(62.72,31.8) 63.03,31.49 63.13,31.39 63.13,30.62 63,30.49 R61.2
$6N2177: length 3.1
  TOP w0.203: v2(65.12,39) 64.32,39 63.92,38.6 U1.L19
  BOTTOM w0.305: R43.1 65.52,38.6 v2(65.12,39) 65.62,39.49 R85.1
$6N2315: length 7.6
  TOP w0.127: R5.2 47.41,48.19 47.72,47.88 47.72,45.21 48.82,44.12 50.4,44.12 U1.E3
$6N2392: length 2.2
  TOP w0.127: R65.2 68.82,37 U1.N23
$7N1408: length 1.2
  TOP w0.305: U1.G17 v2(62.72,42.2)
  BOTTOM w0.305: C250.2 62.59,42.32 v2(62.72,42.2)
$7N1630: length 18.4
  TOP w0.127: v1(79.26,40.77) 79.26,38.77 78.58,38.1 69.18,38.1 67.49,39.79 66.2,39.79 65.92,40.07 65.92,40.38 65.52,40.78 U1.H21
  BOTTOM w0.127: R40.2 v1(79.26,40.77)
$7N1639: length 4.1
  TOP w0.305: U1.D8 v2(55.52,44.6)
  BOTTOM w0.305: v2(55.52,44.6) 56.04,45.12 56.04,46.38 55.79,46.63 R18.2 R87.2
$7N1763: length 1.3
  TOP w0.305: U1.F20 v2(65.12,43)
  BOTTOM w0.305: R32.2 65.22,43.1 v2(65.12,43)
$8N1506: length 1.3
  TOP w0.127: U1.W16 v2(61.12,31.8)
  BOTTOM w0.305: v2(61.12,31.8) 61.07,31.85 R45.1
$8N1514: length 5.6
  TOP w0.114: R36.2 53.15,25.96 53.95,26.76 53.95,29.93 54.32,30.3 U1.AA7
$8N1515: length 5.4
  TOP w0.114: 53.33,25.32 53.33,25.77 54.21,26.65 54.21,28.34 54.33,28.45 54.51,28.45 54.63,28.56 54.63,28.79 54.51,28.91 54.33,28.91 54.21,29.02 54.21,29.69 U1.AB7
$9N2352: length 1.5
  TOP w0.305: U1.T19 v2(64.32,35)
  BOTTOM w0.381: v2(64.32,35) 64.78,34.54 C255.2
$11N1282: length 2.1
  TOP w0.127: U3.L8 v2(35.72,39.85)
  BOTTOM w0.127: R46.2 35.32,40.49 35.45,40.36 35.54,40.28 35.72,40.1 v2(35.72,39.85)
$12N1565: length 1.2
  TOP w0.127: U6.L8 v2(36.52,23.44)
  BOTTOM w0.127: v2(36.52,23.44) 36.59,23.52 R71.2
$13N604: length 2.9
  TOP w0.089: v2(89.92,34.12) 89.27,34.12 U22.K2
  BOTTOM w0.203: v2(89.92,34.12) 89.95,34.12 ; 89.95,34.12 90.33,34.5 C124.1 ; 89.95,34.12 89.31,34.75 C123.1
$13N728: length 1.9
  TOP w0.254: R68.1 87.64,25.53 87.51,25.65 U19.39
$13N772: length 2
  TOP w0.254: R80.2 87.01,25.4 U19.38
$14N447: length 2
  TOP w0.381: U10.3 82.39,71.5 R15.1
$14N448: length 2.8
  TOP w0.381: U10.4 83.88,70.38 R41.2
$14N488:
  vias: v1(89.88,74.42) v1(89.88,73.53) v1(90.77,74.42) v1(90.77,73.53)
$14N520: length 1.4
  TOP w0.381: U12.3 74.78,12.16 R11.1
$14N521: length 1.3
  TOP w0.381: R42.2 73.72,9.03 U12.4
$14N524:
  vias: v1(79.92,8.3) v1(79.92,7.03) v1(81.19,8.3) v1(81.19,7.03)
$14N708: length 5.4
  TOP w0.152: J13.8 83.85,11.49 83.67,11.31 81.2,11.31 80.56,11.95 80.56,12.5 C77.1
$14N709: length 5.5
  TOP w0.152: C81.1 80.23,12.55 80.23,11.81 81.07,10.98 83.48,10.98 83.85,10.61 J13.9
$15N781: length 19.1
  TOP w0.127: v1(20.94,55.55) 21.45,55.04 24.56,55.04 26.84,52.76 R76.2
  BOTTOM w0.127: Q5.1 17.49,59.48 17.49,56.46 17.89,56.05 20.43,56.05 v1(20.94,55.55)
$15N941: length 2.3
  TOP w0.127: v1(65.41,8.35) 65.41,8.3 65.39,8.33 Q2.1
  BOTTOM w0.127: R31.2 65.95,7.64 65.41,8.17 v1(65.41,8.35)
$15N943: length 2.9
  TOP w0.127: Q1.1 68.41,9.29 v1(69.28,10.16)
  BOTTOM w0.127: R22.2 68.91,10.54 v1(69.28,10.16)
$15N992: length 7.9
  TOP w0.254: R2.2 67.39,9.24 Q1.3 67.39,4.62 67.67,4.34 LED1.3
$15N993: length 10.1
  TOP w0.254: LED1.1 62.59,4.19 63.46,5.05 Q2.3 63.46,9.01 64.15,9.7 R34.2
$16N996: length 5.3
  TOP w0.356: U5.5 57.71,67.87 57.69,67.88 C363.1
  TOP w0.381: R229.1 R90.2 R66.1 57.08,68.65 56.99,68.56 C363.1
$16N997: length 2.1
  TOP w0.356: C33.2 57.57,66.74 58.04,67.22 U5.6
$16N998: length 2.7
  TOP w0.356: U5.7 v1(60.11,66.57)
  BOTTOM w0.381: v1(60.11,66.57) 60.19,66.49 C32.1
$16N999: length 2.4
  TOP w0.356: U5.8 v1(63.66,66.57)
  BOTTOM w0.381: C32.2 63.58,66.49 v1(63.66,66.57)
$16N1080: length 2
  TOP w0.381: R49.2 R57.1 R91.2
$16N1087: length 1.3
  TOP w0.381: C351.2 58.77,59.42 R193.1
$16N1088: length 8.9
  TOP w0.254: U5.2 60.33,69.82 61.38,68.77 61.38,66.01 C55.1 59.88,64 59.85,63.98 R27.2
$16N1091: length 3.6
  TOP w0.254: R193.2 C317.1 R27.1 R19.1
$16N1106: length 15.8
  TOP w0.254: R74.2 R146.1 59.73,71.67 58.43,71.67 57.82,71.06 57.82,69.41 58.06,69.17 U5.3 58.98,69.15 60.23,69.15 60.74,68.65 60.74,66.16 60.23,65.65 59.85,65.65 59.09,64.89 59.09,64.53 C55.2 58.45,63.9 R19.2
$16N1113: length 1.4
  TOP w0.254: C350.1 62.71,59.04 R194.2
$16N1114: length 3.6
  TOP w0.254: R20.2 R28.2 C316.1 R194.1
$16N1117: length 8.8
  TOP w0.254: U5.13 63.31,69.82 62.01,68.52 62.01,65.78 61.22,64.99 C54.2 61.22,63.9 61.25,63.87 R28.1
$16N1132: length 14.7
  TOP w0.254: R72.1 R145.1 64.7,71.14 65.52,71.14 65.87,70.78 65.87,69.45 65.59,69.17 U5.12 63.68,69.17 62.77,68.27 62.77,65.53 62.04,64.79 C54.1 62.65,63.9 R20.1
$16N1141: length 2
  TOP w0.305: U5.11 65.82,68.52 66.02,68.72 R49.1
$17N163: length 3.3
  TOP w0.508: T2.7 v1(31.43,66.15)
  BOTTOM w0.381: C297.1 30.92,65.64 v1(31.43,66.15) 32.01,65.57 C154.1
$17N165: length 10
  TOP w0.381: R67.1 20.23,68.06 20.23,76.04 J25.9
$17N167: length 6.3
  TOP w0.114: R59.2 27.52,62.25 27.52,62.49 27.42,62.6 25.38,62.6 24.97,63 24.97,63.37 24.85,63.5 24.1,63.5 23.81,63.79 T2.1
$17N168: length 5.1
  TOP w0.114: R63.2 29.93,62.25 29.93,62.6 30.21,62.88 31.1,62.88 31.32,63.1 31.32,63.37 31.2,63.5 30.45,63.5 30.16,63.79 T2.6
$17N169: length 6.2
  TOP w0.114: R62.2 27.79,62.25 27.79,62.6 27.53,62.87 25.49,62.87 25.24,63.12 25.24,63.37 25.37,63.5 26.13,63.5 26.35,63.72 T2.3
$17N170: length 15.4
  TOP w0.381: R79.1 37.09,76.64 35.72,78.01 33.63,78.01 J25.11
$17N171: length 12.4
  BOTTOM w0.508: R270.2 28.56,78.79 J25.8 30.39,82.65 J25.7
$17N172: length 2.8
  TOP w0.508: T2.15 25.08,72.55 25.33,72.3 v1(25.61,72.3)
  BOTTOM w0.508: v1(25.61,72.3) 25.27,72.64 R271.2
$17N173: length 2.7
  TOP w0.508: T2.10 v1(31.43,72.15)
  BOTTOM w0.508: R269.2 30.93,72.64 v1(31.43,72.15)
$17N175: length 12.8
  TOP w0.254: T2.9 32.7,74.51 32.22,74.99 31.68,74.99 31.1,75.58 26.73,79.94 26.73,80.4 26.91,80.58 28.32,80.58 J25.6
$17N176: length 11.8
  TOP w0.254: T2.11 30.16,74.64 30.59,75.07 30.59,75.51 26.32,79.78 J25.3
$17N178: length 12
  TOP w0.254: T2.16 23.81,74.64 24.04,74.87 24.7,74.87 24.93,75.09 24.93,75.52 25.41,76 25.41,78.14 23.5,80.05 23.5,81.98 24.29,82.76 J25.1
$17N179: length 11.8
  TOP w0.254: T2.14 26.35,74.61 26.12,74.84 25.54,74.84 25.33,75.04 25.33,75.35 25.82,75.83 25.82,78.31 23.91,80.22 23.91,81.81 24.36,82.26 24.68,82.26 J25.2
$17N180: length 11.4
  BOTTOM w0.508: J25.5 28.36,82.65 J25.4 27.34,74.1 26.78,73.54 R272.2
$17N182: length 5.1
  TOP w0.114: R64.2 30.2,62.25 30.2,62.49 30.32,62.61 31.21,62.61 31.59,62.99 31.59,63.37 31.72,63.5 32.48,63.5 32.7,63.72 T2.8
$17N184: length 3.2
  TOP w0.508: T2.2 v1(25.08,66.15)
  BOTTOM w0.381: C153.1 24.7,65.77 v1(25.08,66.15) 25.66,65.57 C307.1
$19N506: length 1.3
  TOP w0.127: R268.1 D19.1

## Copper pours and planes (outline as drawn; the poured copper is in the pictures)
1V1_CORE on TOP (solid shape): 72.92,21.62 72.92,19.4 72.81,19.29 68.93,19.29 68.69,19.05 68.69,18.59 68.44,18.33 67.57,18.33 67.19,17.95 65.41,17.95 65.31,18.05 65.31,21.28 65.8,21.76 72.78,21.76
1V1_CORE on TOP (solid shape): outline of 81 points within 56.47,32.48 63.99,40.38
1V1_CORE on BOTTOM (solid shape): 68.61,21.15 68.61,18.59 68.49,18.46 66.58,18.46 66.46,18.59 66.46,18.92 67.4,18.92 67.4,19.3 67.02,19.3 67.02,18.92 66.46,18.92 66.46,21.26 66.58,21.38 68.39,21.38
1V1_CORE on BOTTOM (solid shape): 63.61,34.34 63.61,33.73 63.99,33.35 63.99,32.61 63.64,32.25 61.88,32.25 61.67,32.47 61.67,32.89 62.32,32.89 62.32,33.27 61.94,33.27 61.94,32.89 61.67,32.89 61.67,33.64 61.68,33.65 62.52,33.65 62.62,33.75 62.62,34.34 62.67,34.39 63.56,34.39
1V1_CORE on BOTTOM (solid shape): 67.95,30.65 67.95,29.79 68.23,29.51 69.68,29.51 69.78,29.41 69.78,27.53 69.66,27.4 69.17,27.4 69,27.22 68.99,27.15 68.99,26.72 68.87,26.59 68.34,26.59 67.88,27.05 68.55,27.05 68.55,27.43 68.17,27.43 68.17,27.05 67.88,27.05 67.29,27.64 67.27,27.67 67.24,27.72 67.2,27.76 67.15,27.79 67.11,27.81 67.05,27.83 67,27.84 66.95,27.84 66.91,27.84 66.87,27.85 66.71,28.01 66.71,29.4 67.18,29.4 67.19,29.35 67.2,29.3 67.22,29.25 67.24,29.2 67.28,29.16 67.32,29.13 67.36,29.1 67.41,29.08 67.46,29.07 67.51,29.06 67.56,29.06 67.61,29.07 67.66,29.09 67.7,29.11 67.75,29.15 67.78,29.18 67.81,29.22 67.83,29.27 67.85,29.32 67.86,29.37 67.86,29.42 67.85,29.47 67.83,29.52 67.81,29.57 67.78,29.61 67.75,29.65 67.7,29.68 67.66,29.71 67.61,29.72 67.56,29.73 67.51,29.73 67.46,29.73 67.41,29.72 67.36,29.69 67.32,29.67 67.28,29.63 67.24,29.59 67.22,29.55 67.2,29.5 67.19,29.45 67.18,29.4 66.71,29.4 66.71,30.63 66.76,30.68 67.93,30.68
1V1_CORE on BOTTOM (solid shape): outline of 87 points within 56.14,35.71 60.56,40.69
1V1_CORE on POWER03 (solid shape): outline of 1643 points within 56.86,19.3 69.82,41.07
1V1_CPU on TOP (solid shape): 74.87,45.88 74.87,42.8 73.37,41.3 73.37,38.61 73.12,38.35 69.56,38.35 69.41,38.5 69.41,41.29 70.8,42.67 70.8,45.94 70.9,46.05 74.7,46.05
1V1_CPU on TOP (solid shape): 62.32,41.49 62.38,41.5 62.72,41.5 62.95,41.27 62.95,38.1 62.53,37.68 62.48,37.64 62.42,37.56 61.4,37.56 61.3,37.67 61.3,38.83 61.38,38.91 61.63,38.91 61.86,39.14 61.86,39.67 61.68,39.85 61.35,39.85 61.3,39.9 61.3,40.29 61.3,40.31 61.32,40.33 61.46,40.6 61.32,40.87 61.3,40.89 61.3,40.91 61.3,41.07 61.73,41.5 62.26,41.5
1V1_CPU on BOTTOM (solid shape): 63.86,40.79 63.86,40.31 63.62,40.06 63.62,38.72 63.74,38.6 63.74,38.07 63.56,37.89 62.46,37.89 61.93,37.89 61.71,38.12 61.71,38.23 63.34,38.23 63.34,38.61 62.96,38.61 62.96,38.23 61.71,38.23 61.71,39.24 63.34,39.24 63.34,39.62 62.96,39.62 62.96,39.24 61.71,39.24 61.71,39.5 62.45,39.5 62.45,39.88 62.07,39.88 62.07,39.5 61.71,39.5 61.71,40.13 63.47,40.13 63.47,40.51 63.09,40.51 63.09,40.13 61.71,40.13 61.71,40.64 61.91,40.84 63.81,40.84
1V1_CPU on BOTTOM (solid shape): 73.57,40.34 73.57,37.63 73.35,37.41 69.28,37.41 69.18,37.52 69.18,37.65 69.2,37.66 68.07,38.79 67.61,38.79 67.47,38.93 67.47,39.12 68.29,39.12 68.29,39.14 68.51,39.14 68.51,39.09 68.51,39.04 68.53,38.98 68.55,38.93 68.58,38.89 68.62,38.85 68.66,38.82 68.71,38.79 68.76,38.77 68.81,38.76 68.87,38.75 68.92,38.76 68.98,38.77 69.03,38.79 69.07,38.82 69.12,38.85 69.15,38.89 69.18,38.93 69.21,38.98 69.22,39.04 69.23,39.09 69.23,39.14 69.22,39.2 69.21,39.25 69.18,39.3 69.15,39.34 69.12,39.38 69.07,39.42 69.03,39.44 68.98,39.46 68.92,39.48 68.87,39.48 68.81,39.48 68.76,39.46 68.71,39.44 68.66,39.42 68.62,39.38 68.58,39.34 68.55,39.3 68.53,39.25 68.51,39.2 68.51,39.14 68.29,39.14 68.29,39.5 67.91,39.5 67.91,39.12 67.47,39.12 67.47,39.52 67.58,39.62 73.25,39.62 73.25,40.01 72.87,40.01 72.87,39.62 67.58,39.62 67.65,39.7 68.54,39.7 69.27,40.43 73.47,40.43
1V1_CPU on POWER03 (solid shape): outline of 327 points within 61.63,38.02 72.81,42.54
1V5_DDR3 on TOP (solid shape): 27.27,46.4 27.27,39.5 27.07,39.29 24.16,39.29 23.99,39.47 23.99,42.13 23.76,42.36 23.22,42.36 23,42.59 23,46.33 23.2,46.53 27.15,46.53
1V5_DDR3 on TOP (solid shape): outline of 88 points within 51.67,30.75 60.13,40.41
1V5_DDR3 on BOTTOM (solid shape): 40.68,43.19 40.68,41.49 40.6,41.42 39.43,41.42 39.35,41.5 39.33,41.54 39.33,42.96 39.64,43.26 40.6,43.26
1V5_DDR3 on BOTTOM (solid shape): 39.34,26.42 39.46,26.29 40.23,26.29 40.35,26.16 40.35,24.51 39.85,24 38.83,24 38.7,24.13 38.7,24.38 39.46,24.38 39.46,24.64 39.08,24.64 39.08,24.38 38.7,24.38 38.7,24.66 38.72,24.68 38.75,24.72 38.77,24.77 38.78,24.82 38.78,24.88 38.78,24.93 38.77,24.98 38.75,25.03 38.72,25.07 38.7,25.09 38.7,25.27 38.58,25.4 38.58,26.29 39.08,26.29 39.08,26.67 38.7,26.67 38.7,26.29 38.58,26.29 38.58,26.92 38.7,27.05 39.34,27.05
1V5_DDR3 on BOTTOM (solid shape): 56.52,34.36 56.52,33.6 56.63,33.5 58.45,33.5 58.61,33.65 60.28,33.65 60.41,33.52 60.41,32.99 60.38,32.96 55.3,32.96 55.25,33.02 55.25,33.07 59.98,33.07 59.98,33.32 59.72,33.32 59.72,33.07 58.58,33.07 58.58,33.32 58.33,33.32 58.33,33.07 55.25,33.07 55.25,33.45 56.04,33.45 56.04,33.7 55.66,33.7 55.66,33.45 55.25,33.45 55.25,33.83 56.04,33.83 56.04,34.08 55.66,34.08 55.66,33.83 55.25,33.83 55.25,34.36 55.33,34.44 56.45,34.44
1V5_DDR3 on BOTTOM (solid shape): 54.24,39.77 54.24,37.89 54.26,37.86 54.26,33.7 54.09,33.52 54.09,30.91 53.96,30.78 53.5,30.78 53.37,30.65 53.37,30.04 53.27,29.94 51.4,29.94 51.28,30.07 51.28,30.35 52.8,30.35 52.8,30.75 52.43,30.75 52.43,30.35 51.28,30.35 51.28,31.11 53.69,31.11 53.69,31.5 53.31,31.5 53.31,31.11 51.28,31.11 51.28,31.49 51.79,32 53.69,32 53.69,32.38 53.31,32.38 53.31,32 51.79,32 52.68,32.89 53.69,32.89 53.69,33.27 53.31,33.27 53.31,32.89 52.68,32.89 52.81,33.02 52.81,33.39 53.31,33.9 53.33,33.91 53.37,33.95 53.41,33.99 53.42,34.01 53.55,34.14 53.55,35.05 54.07,35.05 54.07,35.43 53.69,35.43 53.69,35.05 53.55,35.05 53.55,37.26 54.01,37.26 54.01,37.51 53.76,37.51 53.76,37.26 53.55,37.26 53.55,37.99 53.49,38.06 53.49,38.53 54.01,38.53 54.01,38.78 53.76,38.78 53.76,38.53 53.49,38.53 53.49,38.77 53.55,38.83 53.55,39.75 53.5,39.8 52.92,39.8 52.92,39.92 53.63,39.92 53.63,40.18 53.37,40.18 53.37,39.92 52.92,39.92 52.92,40.31 52.94,40.33 53.68,40.33
1V5_DDR3 on POWER03 (solid shape): outline of 6771 points within 25.88,11.05 62.45,47.88
3V3 on TOP (solid shape): 76.29,51.17 76.29,49.14 76.17,49.02 75.15,49.02 74.9,49.28 73.16,49.28 73.07,49.36 73.07,50.23 73.1,50.26 74.82,50.26 74.91,50.35 74.91,51.18 75.03,51.31 76.15,51.31
3V3 on TOP (solid shape): 71.54,8.61 71.54,6.65 71.41,6.52 69.88,6.52 69.76,6.65 69.76,6.9 71.03,6.9 71.03,7.29 70.77,7.29 70.77,6.9 70.52,6.9 70.52,7.29 70.27,7.29 70.27,6.9 69.76,6.9 69.76,8.57 69.92,8.74 71.41,8.74
3V3 on TOP (solid shape): 17.38,46.63 17.38,44.45 17.15,44.22 17.15,42.11 17.1,42.06 15.02,42.06 14.92,42.16 14.92,43.05 16.73,43.05 16.73,43.43 16.35,43.43 16.35,43.05 14.92,43.05 14.92,43.69 16.73,43.69 16.73,44.07 16.35,44.07 16.35,43.69 14.92,43.69 14.92,46.58 15.1,46.76 17.26,46.76
3V3 on TOP (solid shape): 77.31,63.88 77.31,62.36 77.18,62.23 71.21,62.23 70.83,61.85 68.67,61.85 68.55,61.98 68.55,62.23 70.58,62.23 70.58,62.74 70.07,62.74 70.07,62.23 68.55,62.23 68.55,62.99 68.93,63.37 69.82,63.37 70.71,64.26 76.93,64.26
3V3 on TOP (solid shape): 68.06,12.95 69.15,12.95 69.25,12.85 69.25,11.22 68.39,10.36 68.37,10.36 68.27,10.26 67.3,10.26 67.28,10.29 67.25,10.33 67.21,10.37 67.17,10.4 67.12,10.43 67.07,10.45 67.02,10.46 66.96,10.46 66.91,10.46 66.86,10.45 66.8,10.43 66.76,10.4 66.71,10.37 66.67,10.33 66.64,10.29 66.63,10.26 65.73,10.26 65.73,10.77 65.31,11.19 65.31,12.19 67.53,12.19 67.53,12.7 67.02,12.7 67.02,12.19 65.31,12.19 65.31,12.92 65.44,13.05 67.95,13.05
3V3 on BOTTOM (solid shape): 17.36,46.53 17.36,44.37 17.2,44.22 14.99,44.22 14.87,44.34 14.87,46.53 15.02,46.68 17.2,46.68
3V3 on BOTTOM (solid shape): 73.06,9.19 73.06,7.29 72.93,7.16 69.38,7.16 69.25,7.29 69.25,7.83 70.74,9.32 72.93,9.32
3V3 on BOTTOM (solid shape): 68.62,11.57 68.62,11.17 68.47,11.02 65.81,11.02 65.68,11.15 65.68,12.95 65.85,13.13 67.07,13.13
3V3 on BOTTOM (solid shape): 66.7,32.87 66.71,32.85 66.71,31.29 66.43,31.01 65.24,31.01 64.85,31.39 64.85,31.75 65.63,31.75 65.63,32.13 65.25,32.13 65.25,31.75 64.85,31.75 64.85,32.79 64.98,32.91 66.66,32.91
3V3 on BOTTOM (solid shape): 78.8,58.32 82.79,58.32 84.17,56.94 86.22,56.94 86.36,56.8 86.36,54.2 86.18,54.02 84.5,54.02 82.77,55.75 80.61,55.75 80.23,55.37 80.23,51.82 79.98,51.56 76.55,51.56 76.29,51.31 76.29,49.15 76.17,49.02 75.02,49.02 74.77,49.28 74.77,51.94 75.91,53.09 77.56,53.09 77.89,53.41 77.89,55.43 72.48,60.83 70.83,60.83 70.71,60.71 68.67,60.71 68.42,60.96 68.42,61.21 69.44,61.21 69.44,61.19 69.44,61.13 69.46,61.08 69.48,61.03 69.52,60.98 69.55,60.94 69.6,60.9 69.64,60.87 69.69,60.85 69.75,60.84 69.8,60.83 69.86,60.83 69.91,60.84 69.97,60.86 70.02,60.89 70.06,60.92 70.1,60.96 70.14,61 70.16,61.05 70.18,61.1 70.2,61.16 70.2,61.21 70.2,61.27 70.18,61.32 70.16,61.38 70.14,61.42 70.1,61.47 70.06,61.51 70.02,61.54 69.97,61.57 69.91,61.58 69.86,61.59 69.8,61.6 69.75,61.59 69.69,61.58 69.64,61.55 69.6,61.52 69.55,61.49 69.52,61.45 69.48,61.4 69.46,61.35 69.44,61.3 69.44,61.24 69.44,61.21 68.42,61.21 68.42,62.99 68.67,63.25 73.88,63.25
3V3 on POWER03 (solid shape): outline of 7873 points within 11.91,3.89 90.84,59.41
3V3_MOS on TOP (solid shape): 78.2,45.72 78.2,42.93 78.07,42.8 75.41,42.8 75.28,42.93 75.28,45.72 75.41,45.85 78.07,45.85
3V3_MOS on TOP (solid shape): 53.37,43.07 54.31,43.07 55.38,42.01 55.38,41.7 55.28,41.6 54.42,41.6 53.89,42.12 53.44,42.12 53.15,42.41 52.64,42.41 52.54,42.52 52.54,42.74 52.99,43.2 53.25,43.2
3V3_MOS on TOP (solid shape): 58.97,43.9 58.97,43.11 58.84,42.97 56.83,42.97 56.65,42.79 56.4,42.79 56.27,42.92 56.27,43.18 56.5,43.4 56.5,44.27 56.65,44.42 58.45,44.42
3V3_MOS on TOP (solid shape): 63.76,43.1 63.76,42.92 63.56,42.72 63.56,42.45 63.75,42.26 63.75,42.05 63.74,42.04 63.65,41.93 63.62,41.8 63.69,41.59 63.89,41.49 63.91,41.49 64.02,41.49 64.14,41.37 64.14,40.13 63.63,39.61 63.63,39.49 63.63,39.49 63.62,39.39 63.63,39.3 63.64,39.29 63.64,38.71 63.63,38.7 63.62,38.58 63.65,38.46 63.65,38.45 63.65,38.36 64.54,37.47 64.54,37.3 64.04,36.8 63.66,36.8 63.1,37.36 63.1,41.37 62.96,41.51 62.96,41.94 63.05,42.06 63.08,42.21 63.08,42.36 62.9,42.54 62.87,42.54 62.87,43.48 63,43.61 63.25,43.61
3V3_MOS on BOTTOM (solid shape): 18.38,53.89 18.38,52.88 18.25,52.75 16.98,52.75 16.85,52.88 16.85,53.89 16.98,54.02 18.25,54.02
3V3_MOS on BOTTOM (solid shape): 24.55,27.1 24.55,25.45 24.42,25.32 21.75,25.32 21.62,25.45 21.62,27.1 21.75,27.22 24.42,27.22
3V3_MOS on BOTTOM (solid shape): 74.2,11.48 74.2,9.7 74.08,9.57 72.32,9.57 72.17,9.72 72.17,11.37 72.4,11.6 74.08,11.6
3V3_MOS on BOTTOM (solid shape): 55.48,42.01 55.48,40.25 55.47,40.24 54.63,40.24 54.62,40.25 54.62,41.44 54.31,41.74 54.31,42.01 54.4,42.1 55.39,42.1
3V3_MOS on BOTTOM (solid shape): 66.46,37.59 66.46,36.8 66.4,36.75 65.62,36.75 65.39,36.98 64.22,36.98 64.07,37.13 65.44,37.13 65.44,37.38 65.19,37.38 65.19,37.13 64.07,37.13 64.07,37.61 66.43,37.61
3V3_MOS on BOTTOM (solid shape): 51.82,44.39 51.82,43.56 51.95,43.43 53.22,43.43 53.35,43.3 53.35,42.79 53.3,42.74 52.87,42.74 52.64,42.97 51.22,42.97 51.14,43.05 51.14,43.43 51.66,43.43 51.66,44.07 51.4,44.07 51.4,43.43 51.14,43.43 51.14,44.45 51.19,44.5 51.72,44.5
